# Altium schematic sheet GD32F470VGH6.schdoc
size 127 x 101 mm
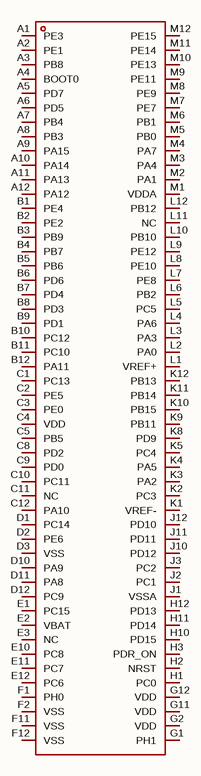
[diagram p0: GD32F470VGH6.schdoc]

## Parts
U?  gd32f470vgh6  [BGA-100_L7.0-W7.0-P0.50-TL_GIGADEVICE_GD32F450]  (value not drawn)

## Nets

Not connected (* = marked no-connect by the designer): U? A1(PE3) A2(PE1) A3(PB8) A4(BOOT0) A5(PD7) A6(PD5) A7(PB4) A8(PB3) A9(PA15) A10(PA14) A11(PA13) A12(PA12) B1(PE4) B2(PE2) B3(PB9) B4(PB7) B5(PB6) B6(PD6) B7(PD4) B8(PD3) B9(PD1) B10(PC12) B11(PC10) B12(PA11) C1(PC13) C2(PE5) C3(PE0) C4(VDD) C5(PB5) C8(PD2) C9(PD0) C10(PC11) C11(NC) C12(PA10) D1(PC14) D2(PE6) D3(VSS) D10(PA9) D11(PA8) D12(PC9) E1(PC15) E2(VBAT) E3(NC) E10(PC8) E11(PC7) E12(PC6) F1(PH0) F2(VSS) F11(VSS) F12(VSS) G1(PH1) G2(VDD) G11(VDD) G12(VDD) H1(PC0) H2(NRST) H3(PDR_ON) H10(PD15) H11(PD14) H12(PD13) J1(VSSA) J2(PC1) J3(PC2) J10(PD12) J11(PD11) J12(PD10) K1(VREF-) K2(PC3) K3(PA2) K4(PA5) K5(PC4) K8(PD9) K9(PB11) K10(PB15) K11(PB14) K12(PB13) L1(VREF+) L2(PA0) L3(PA3) L4(PA6) L5(PC5) L6(PB2) L7(PE8) L8(PE10) L9(PE12) L10(PB10) L11(NC) L12(PB12) M1(VDDA) M2(PA1) M3(PA4) M4(PA7) M5(PB0) M6(PB1) M7(PE7) M8(PE9) M9(PE11) M10(PE13) M11(PE14) M12(PE15)

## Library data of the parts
U? = gd32f470vgh6: CPU内核:ARM Cortex-M系列;CPU最大主频:240MHz;; Manufacturer: GigaDevice(兆易创新); AddInBom: yes; ModelId: 03ebc77588d74bb8a70f1b4fbf2a18a9; ModelName: BGA-100_L7.0-W7.0-H0.7-P0.50-TL_GD32F407VKH6; ModelTransform: 275.59,275.59,0,0,0,0,0,0,0; CPU Maximum Speed: 240MHz; Program Storage Size: 1MB; Program Memory Type: FLASH; Number of I/O: 140; ADC (Bit): 10bit；8bit；6bit；12bit; DAC (Bit): 12bit; Voltage - Supply: 2.6V~3.6V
